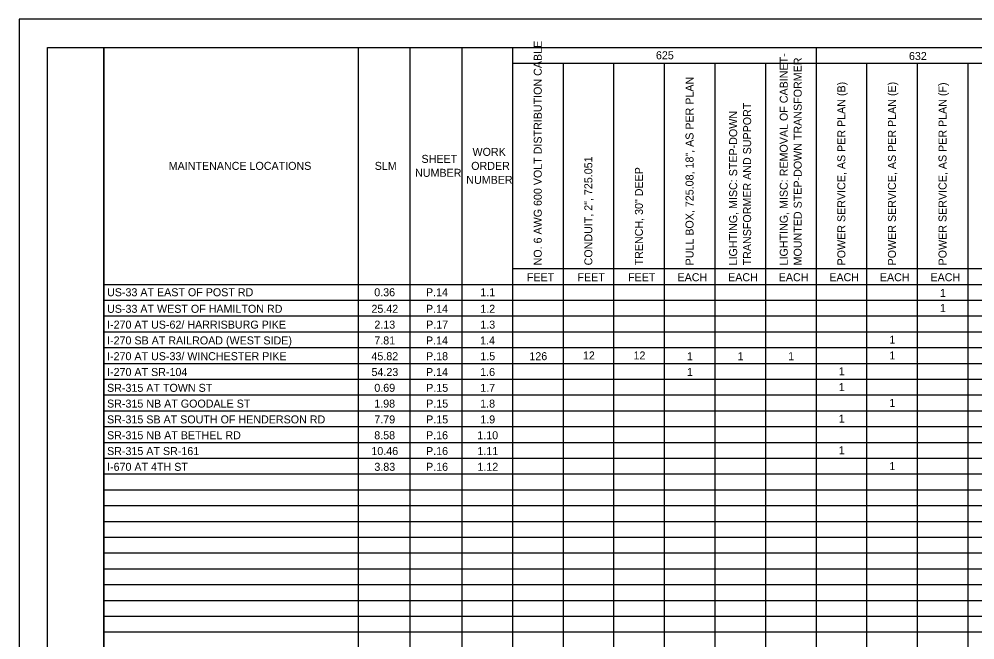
# Model space of a CAD drawing. Extents: x 0 to 34, y 0 to 22.
# Drawn here: x 0 to 16.91, y 11.01 to 22 of the extents above; entities that cross this region are included whole.
import ezdxf

# ---------------------------------------------------------------- set-up
doc = ezdxf.new("R2010")
doc.units = 0
for name, color, linetype in [('Default', 7, 'Continuous'), ('SH_Border', 7, 'Continuous'), ('SH_Cut_Line', 7, 'Continuous')]:
    doc.layers.add(name, color=color, linetype=linetype)

msp = doc.modelspace()

# ---------------------------------------------------------------- linework, layer by layer
at = {"layer": 'Default'}
for p, q in [((1.5, 21.5), (4.208, 21.5)), ((1.5, 21.5), (1.5, 0.801)), ((4.208, 21.5), (6.915, 21.5)), ((5.998, 21.5), (5.998, 1.081)), ((6.915, 21.5), (7.833, 21.5)), ((6.915, 21.5), (6.915, 1.081)), ((7.833, 21.5), (21.259, 21.5)), ((7.833, 21.5), (7.833, 1.081)), ((8.728, 21.5), (8.728, 0.801)), ((14.098, 21.5), (14.098, 0.801)), ((8.728, 21.22), (21.259, 21.22)), ((9.623, 21.22), (9.623, 0.801)), ((10.518, 21.22), (10.518, 0.801)), ((11.413, 21.22), (11.413, 0.801)), ((12.308, 21.22), (12.308, 0.801)), ((13.203, 21.22), (13.203, 0.801)), ((14.993, 21.22), (14.993, 0.801)), ((15.888, 21.22), (15.888, 0.801)), ((16.784, 21.22), (16.784, 0.801)), ((8.728, 17.584), (21.259, 17.584)), ((1.5, 17.304), (4.208, 17.304)), ((4.208, 17.304), (6.915, 17.304)), ((6.915, 17.304), (7.833, 17.304)), ((7.833, 17.304), (21.259, 17.304)), ((1.5, 17.025), (4.208, 17.025)), ((4.208, 17.025), (6.915, 17.025)), ((6.915, 17.025), (7.833, 17.025)), ((7.833, 17.025), (21.259, 17.025)), ((1.5, 16.745), (4.208, 16.745)), ((4.208, 16.745), (6.915, 16.745)), ((6.915, 16.745), (7.833, 16.745)), ((7.833, 16.745), (21.259, 16.745)), ((1.5, 16.465), (4.208, 16.465)), ((4.208, 16.465), (6.915, 16.465)), ((6.915, 16.465), (7.833, 16.465)), ((7.833, 16.465), (21.259, 16.465)), ((1.5, 16.185), (4.208, 16.185)), ((4.208, 16.185), (6.915, 16.185)), ((6.915, 16.185), (7.833, 16.185)), ((7.833, 16.185), (21.259, 16.185)), ((1.5, 15.906), (4.208, 15.906)), ((4.208, 15.906), (6.915, 15.906)), ((6.915, 15.906), (7.833, 15.906)), ((7.833, 15.906), (21.259, 15.906)), ((1.5, 15.626), (4.208, 15.626)), ((4.208, 15.626), (6.915, 15.626)), ((6.915, 15.626), (7.833, 15.626)), ((7.833, 15.626), (21.259, 15.626)), ((1.5, 15.346), (4.208, 15.346)), ((4.208, 15.346), (6.915, 15.346)), ((6.915, 15.346), (7.833, 15.346)), ((7.833, 15.346), (21.259, 15.346)), ((1.5, 15.067), (4.208, 15.067)), ((4.208, 15.067), (6.915, 15.067)), ((6.915, 15.067), (7.833, 15.067)), ((7.833, 15.067), (21.259, 15.067)), ((1.5, 14.787), (4.208, 14.787)), ((4.208, 14.787), (6.915, 14.787)), ((6.915, 14.787), (7.833, 14.787)), ((7.833, 14.787), (21.259, 14.787)), ((1.5, 14.507), (4.208, 14.507)), ((4.208, 14.507), (6.915, 14.507)), ((6.915, 14.507), (7.833, 14.507)), ((7.833, 14.507), (21.259, 14.507)), ((1.5, 14.227), (4.208, 14.227)), ((4.208, 14.227), (6.915, 14.227)), ((6.915, 14.227), (7.833, 14.227)), ((7.833, 14.227), (21.259, 14.227)), ((1.5, 13.948), (4.208, 13.948)), ((4.208, 13.948), (6.915, 13.948)), ((6.915, 13.948), (7.833, 13.948)), ((7.833, 13.948), (21.259, 13.948)), ((1.5, 13.668), (4.208, 13.668)), ((4.208, 13.668), (6.915, 13.668)), ((6.915, 13.668), (7.833, 13.668)), ((7.833, 13.668), (21.259, 13.668)), ((1.5, 13.388), (4.208, 13.388)), ((4.208, 13.388), (6.915, 13.388)), ((6.915, 13.388), (7.833, 13.388)), ((7.833, 13.388), (21.259, 13.388)), ((1.5, 13.109), (4.208, 13.109)), ((4.208, 13.109), (6.915, 13.109)), ((6.915, 13.109), (7.833, 13.109)), ((7.833, 13.109), (21.259, 13.109)), ((1.5, 12.829), (4.208, 12.829)), ((4.208, 12.829), (6.915, 12.829)), ((6.915, 12.829), (7.833, 12.829)), ((7.833, 12.829), (21.259, 12.829)), ((1.5, 12.549), (4.208, 12.549)), ((4.208, 12.549), (6.915, 12.549)), ((6.915, 12.549), (7.833, 12.549)), ((7.833, 12.549), (21.259, 12.549)), ((1.5, 12.269), (4.208, 12.269)), ((4.208, 12.269), (6.915, 12.269)), ((6.915, 12.269), (7.833, 12.269)), ((7.833, 12.269), (21.259, 12.269)), ((1.5, 11.99), (4.208, 11.99)), ((4.208, 11.99), (6.915, 11.99)), ((6.915, 11.99), (7.833, 11.99)), ((7.833, 11.99), (21.259, 11.99)), ((1.5, 11.71), (4.208, 11.71)), ((4.208, 11.71), (6.915, 11.71)), ((6.915, 11.71), (7.833, 11.71)), ((7.833, 11.71), (21.259, 11.71)), ((1.5, 11.43), (4.208, 11.43)), ((4.208, 11.43), (6.915, 11.43)), ((6.915, 11.43), (7.833, 11.43)), ((7.833, 11.43), (21.259, 11.43)), ((1.5, 11.151), (4.208, 11.151)), ((4.208, 11.151), (6.915, 11.151)), ((6.915, 11.151), (7.833, 11.151)), ((7.833, 11.151), (21.259, 11.151))]:
    msp.add_line(p, q, dxfattribs=at)
at = {"layer": 'SH_Border'}
for points in [[(0.5, 21.5), (1.5, 21.5), (1.5, 0.5), (0.5, 0.5)], [(1.5, 21.5), (33.5, 21.5), (33.5, 0.5), (1.5, 0.5)]]:
    msp.add_lwpolyline(points, close=True, dxfattribs=at)
at = {"layer": 'SH_Cut_Line'}
msp.add_lwpolyline([(0, 0), (34, 0), (34, 22), (0, 22)], close=True, dxfattribs=at)

# ---------------------------------------------------------------- texts
at = {"layer": 'Default'}
for s, p in [('NO. 6 AWG 600 VOLT DISTRIBUTION CABLE', (9.246, 17.64)), ('LIGHTING, MISC: REMOVAL OF CABINET-', (13.598, 17.64)), ('MOUNTED STEP-DOWN TRANSFORMER', (13.845, 17.64)), ('PULL BOX, 725.08, 18", AS PER PLAN', (11.931, 17.64)), ('POWER SERVICE, AS PER PLAN (B)', (14.617, 17.64)), ('POWER SERVICE, AS PER PLAN (E)', (15.512, 17.64)), ('POWER SERVICE, AS PER PLAN (F)', (16.407, 17.64)), ('TRANSFORMER AND SUPPORT', (12.95, 17.64)), ('LIGHTING, MISC: STEP-DOWN ', (12.703, 17.64)), ('CONDUIT, 2", 725.051', (10.141, 17.64)), ('TRENCH, 30" DEEP', (11.036, 17.64))]:
    msp.add_text(s, height=0.14154, rotation=90, dxfattribs=at).set_placement(p)
for s, height, p in [('625', 0.1415, (11.266, 21.289)), ('632', 0.1415, (15.742, 21.276)), ('WORK ', 0.1415, (8.021, 19.579)), ('MAINTENANCE LOCATIONS', 0.14154, (2.646, 19.331)), ('SLM', 0.1415, (6.291, 19.331)), ('SHEET ', 0.1415, (7.119, 19.455)), ('ORDER ', 0.1415, (7.998, 19.331)), ('NUMBER', 0.1415, (7.005, 19.208)), ('NUMBER', 0.1415, (7.911, 19.084)), ('FEET', 0.1415, (8.983, 17.36)), ('FEET', 0.1415, (9.878, 17.36)), ('FEET', 0.1415, (10.773, 17.36)), ('EACH', 0.1415, (11.648, 17.36)), ('EACH', 0.1415, (12.543, 17.36)), ('EACH', 0.1415, (13.438, 17.36)), ('EACH', 0.1415, (14.333, 17.36)), ('EACH', 0.1415, (15.228, 17.36)), ('EACH', 0.1415, (16.123, 17.36)), ('US-33 AT EAST OF POST RD', 0.14154, (1.556, 17.094)), ('0.36', 0.1415, (6.283, 17.094)), ('P.14', 0.1415, (7.198, 17.094)), ('1.1', 0.1415, (8.159, 17.094)), ('1', 0.142, (16.291, 17.081)), ('US-33 AT WEST OF HAMILTON RD', 0.14154, (1.556, 16.801)), ('25.42', 0.1415, (6.233, 16.801)), ('P.14', 0.1415, (7.198, 16.801)), ('1.2', 0.1415, (8.159, 16.801)), ('1', 0.142, (16.291, 16.814)), ('I-270 AT US-62/ HARRISBURG PIKE', 0.14154, (1.556, 16.521)), ('2.13', 0.1415, (6.285, 16.521)), ('P.17', 0.1415, (7.2, 16.521)), ('1.3', 0.1415, (8.159, 16.521)), ('I-270 SB AT RAILROAD (WEST SIDE)', 0.14154, (1.556, 16.241)), ('7.81', 0.1415, (6.284, 16.241)), ('P.14', 0.1415, (7.198, 16.241)), ('1.4', 0.1415, (8.156, 16.241)), ('1', 0.142, (15.396, 16.255)), ('I-270 AT US-33/ WINCHESTER PIKE', 0.14154, (1.556, 15.962)), ('45.82', 0.1415, (6.233, 15.962)), ('P.18', 0.1415, (7.199, 15.962)), ('1.5', 0.1415, (8.159, 15.962)), ('126', 0.1415, (9.027, 15.962)), ('12', 0.1415, (9.974, 15.975)), ('12', 0.1415, (10.869, 15.975)), ('1', 0.142, (11.815, 15.962)), ('1', 0.142, (12.71, 15.962)), ('1', 0.142, (13.605, 15.962)), ('1', 0.142, (15.396, 15.975)), ('I-270 AT SR-104', 0.14154, (1.556, 15.682)), ('54.23', 0.1415, (6.234, 15.682)), ('P.14', 0.1415, (7.198, 15.682)), ('1.6', 0.1415, (8.157, 15.682)), ('1', 0.142, (11.815, 15.682)), ('1', 0.142, (14.5, 15.695)), ('1', 0.142, (14.5, 15.415)), ('SR-315 AT TOWN ST', 0.14154, (1.556, 15.402)), ('0.69', 0.1415, (6.284, 15.402)), ('P.15', 0.1415, (7.201, 15.402)), ('1.7', 0.1415, (8.158, 15.402)), ('SR-315 NB AT GOODALE ST', 0.14154, (1.556, 15.123)), ('1.98', 0.1415, (6.283, 15.123)), ('P.15', 0.1415, (7.201, 15.123)), ('1.8', 0.1415, (8.157, 15.123)), ('1', 0.142, (15.396, 15.136)), ('SR-315 SB AT SOUTH OF HENDERSON RD', 0.14154, (1.556, 14.843)), ('7.79', 0.1415, (6.284, 14.843)), ('P.15', 0.1415, (7.201, 14.843)), ('1.9', 0.1415, (8.158, 14.843)), ('1', 0.142, (14.5, 14.856)), ('SR-315 NB AT BETHEL RD', 0.14154, (1.556, 14.563)), ('8.58', 0.1415, (6.283, 14.563)), ('P.16', 0.1415, (7.199, 14.563)), ('1.10', 0.1415, (8.106, 14.563)), ('SR-315 AT SR-161', 0.14154, (1.556, 14.283)), ('10.46', 0.1415, (6.232, 14.283)), ('P.16', 0.1415, (7.199, 14.283)), ('1.11', 0.1415, (8.108, 14.283)), ('1', 0.142, (14.5, 14.297)), ('I-670 AT 4TH ST', 0.14154, (1.556, 14.004)), ('3.83', 0.1415, (6.285, 14.004)), ('P.16', 0.1415, (7.199, 14.004)), ('1.12', 0.1415, (8.108, 14.004)), ('1', 0.142, (15.396, 14.017))]:
    msp.add_text(s, height=height, dxfattribs=at).set_placement(p)

doc.saveas('drawing.dxf')
